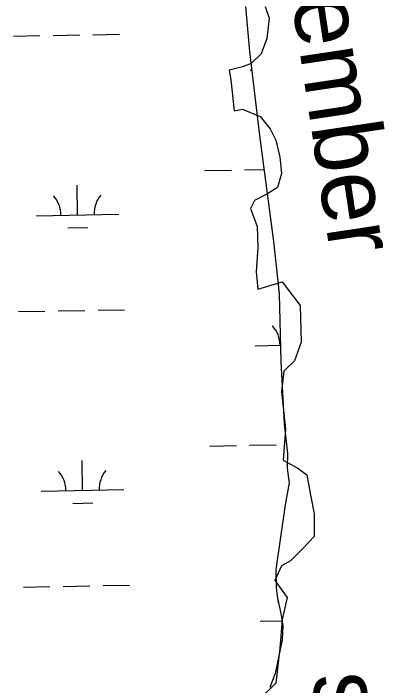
# Model space of a CAD drawing. Extents: x 3925854 to 3964121, y 224593 to 250589.
# Drawn here: x 3947373 to 3947821, y 234463 to 235275 of the extents above; entities that cross this region are included whole.
import ezdxf

# ---------------------------------------------------------------- set-up
doc = ezdxf.new("R2010")
doc.units = 0
for name, color, linetype in [('V-RIVR-EDGE', 7, 'Continuous'), ('V-RIVR-IDEN', 7, 'Continuous'), ('V-WETL-SWMP', 7, 'Continuous')]:
    doc.layers.add(name, color=color, linetype=linetype)

msp = doc.modelspace()

# ---------------------------------------------------------------- linework, layer by layer
at = {"layer": 'V-RIVR-EDGE'}
msp.add_lwpolyline([(3947676.743, 235282.807), (3947681.657, 235269.046), (3947678.709, 235244.474), (3947671.829, 235225.799), (3947660.034, 235214.004), (3947649.222, 235210.072), (3947633.496, 235206.141), (3947635.461, 235194.346), (3947639.393, 235156.996), (3947649.222, 235158.962), (3947670.846, 235150.116), (3947682.64, 235135.372), (3947689.521, 235121.612), (3947694.435, 235100.971), (3947696.401, 235081.313), (3947691.486, 235064.604), (3947679.692, 235056.741), (3947663.965, 235048.877), (3947659.051, 235039.049), (3947666.914, 235017.425), (3947667.897, 234991.87), (3947665.931, 234962.383), (3947667.897, 234941.742), (3947678.709, 234944.691), (3947697.384, 234950.588), (3947719.008, 234922.084), (3947719.99, 234877.854), (3947712.127, 234855.247), (3947699.35, 234842.469), (3947696.401, 234817.897), (3947701.315, 234772.684), (3947698.367, 234735.334), (3947716.059, 234725.505), (3947726.871, 234717.642), (3947731.785, 234691.103), (3947735.717, 234670.463), (3947735.717, 234642.941), (3947722.939, 234629.181), (3947707.213, 234613.455), (3947696.401, 234607.557), (3947688.538, 234589.865), (3947703.281, 234569.224), (3947697.384, 234542.686), (3947694.435, 234508.285), (3947689.521, 234466.02), (3947670.846, 234447.345)], dxfattribs=at)
at = {"layer": 'V-WETL-SWMP'}
for p, q in [((3947372.991, 235247.173), (3947404.986, 235247.754)), ((3947420.983, 235248.045), (3947452.978, 235248.627)), ((3947468.975, 235248.918), (3947500.97, 235249.5)), ((3947658.632, 235205.929), (3947660.544, 235205.964)), ((3947603.98, 235084.844), (3947635.975, 235085.426)), ((3947651.972, 235085.717), (3947675.211, 235086.139)), ((3947450.336, 235031.3), (3947449.682, 235067.294)), ((3947400.344, 235030.391), (3947500.328, 235032.209)), ((3947438.619, 235015.654), (3947462.615, 235016.09)), ((3947379.039, 234914.553), (3947411.034, 234915.134)), ((3947427.031, 234915.425), (3947459.026, 234916.007)), ((3947475.023, 234916.298), (3947507.018, 234916.88)), ((3947664.68, 234873.309), (3947695.082, 234873.862)), ((3947610.028, 234752.224), (3947642.023, 234752.806)), ((3947658.02, 234753.097), (3947690.015, 234753.679)), ((3947456.384, 234698.68), (3947455.73, 234734.674)), ((3947406.393, 234697.771), (3947506.376, 234699.589)), ((3947444.667, 234683.034), (3947468.663, 234683.47)), ((3947385.087, 234581.933), (3947417.082, 234582.514)), ((3947433.079, 234582.805), (3947465.074, 234583.387)), ((3947481.071, 234583.678), (3947513.066, 234584.26)), ((3947670.728, 234540.689), (3947697.113, 234541.169))]:
    msp.add_line(p, q, dxfattribs=at)
msp.add_lwpolyline([(3947652.98, 235283.104), (3947657.858, 235228.811), (3947669.805, 235127.193), (3947686.651, 234999.271), (3947693.512, 234936.205), (3947695.574, 234854.311), (3947699.474, 234779.039), (3947703.549, 234743.3), (3947703.326, 234726.509), (3947704.278, 234719.15), (3947705.529, 234707.937), (3947700.974, 234681.059), (3947689.796, 234603.188), (3947690.198, 234580.792), (3947691.785, 234568.526), (3947695.737, 234549.931), (3947697.995, 234535.556), (3947697.064, 234518.076), (3947688.83, 234477.601), (3947682.306, 234460.545)], dxfattribs=at)
for centre, start, end in [((3947395.094, 235030.771), 0.269879, 41.813537), ((3947505.561, 235032.779), 140.269876, 181.813534), ((3947659.429, 234873.688), 0.269879, 41.813537), ((3947401.142, 234698.151), 0.269879, 41.813537), ((3947511.609, 234700.159), 140.269876, 181.813534), ((3947665.477, 234541.068), 38.867824, 41.813537)]:
    msp.add_arc(centre, 35.246, start, end, dxfattribs=at)

# ---------------------------------------------------------------- texts
at = {"layer": 'V-RIVR-IDEN'}
for s, rotation, p in [('September', 278.552938, (3947674.912, 235517.257)), ('Photos', 91.763137, (3947809.079, 234134.674))]:
    msp.add_text(s, height=82.9998, rotation=rotation, dxfattribs=at).set_placement(p)

doc.saveas('drawing.dxf')
